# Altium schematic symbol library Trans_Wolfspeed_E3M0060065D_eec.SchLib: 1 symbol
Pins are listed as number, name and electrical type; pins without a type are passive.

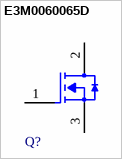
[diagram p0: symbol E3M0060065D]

## E3M0060065D
designator Q?  (value not drawn)
pins: 1 Gate, 2 Drain, 3 Source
